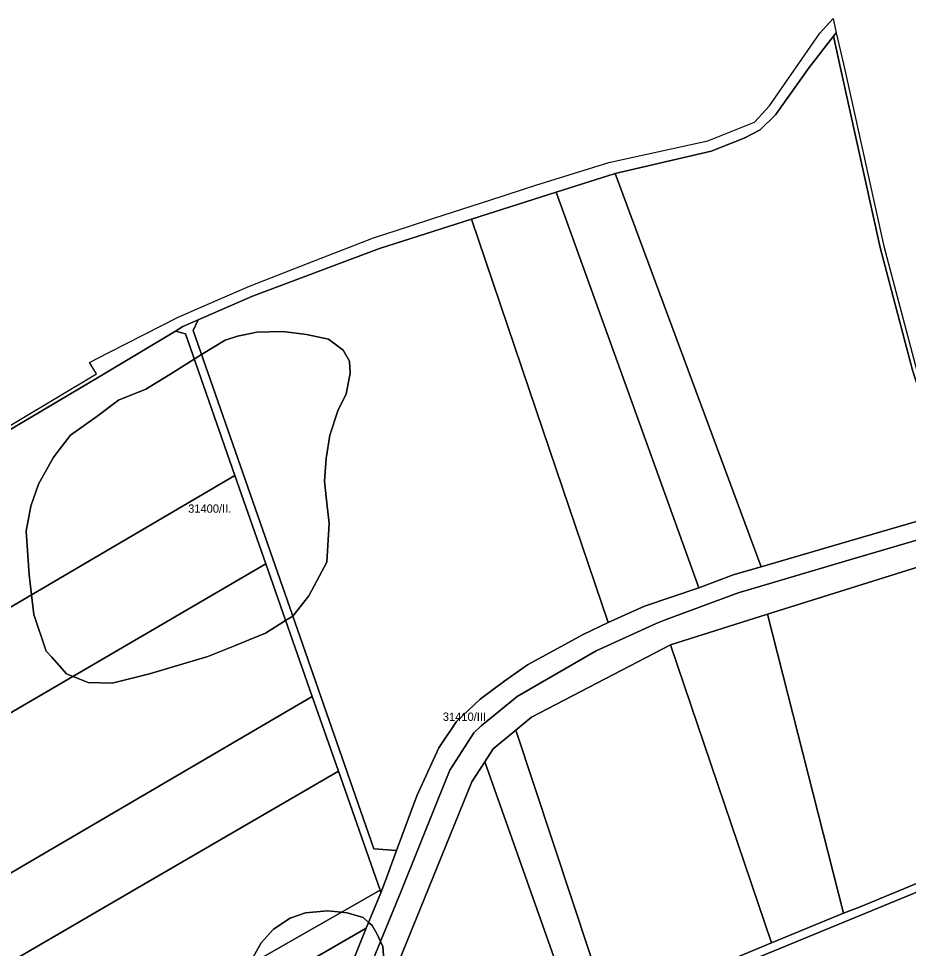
# Model space of a CAD drawing. Extents: x -522079 to -518833, y -1142400 to -1139961.
# Drawn here: x -520538 to -520002, y -1140521 to -1139961 of the extents above; entities that cross this region are included whole.
import ezdxf

# ---------------------------------------------------------------- set-up
doc = ezdxf.new("R2010")
doc.units = 0
for name, color, linetype in [('95560013', 7, 'Continuous'), ('95610013', 7, 'Continuous'), ('95640013', 7, 'Continuous'), ('95660013', 7, 'Continuous')]:
    doc.layers.add(name, color=color, linetype=linetype)

msp = doc.modelspace()

# ---------------------------------------------------------------- linework, layer by layer
at = {"layer": '95560013'}
for points in [[(-520178.95, -1140054.65), (-520121.19, -1140041.17), (-520101.17, -1140033.45), (-520091.68, -1140028.41), (-520082.48, -1140019.36), (-520062.19, -1139990.92), (-520047.4, -1139971.94), (-520042.94, -1139993.02), (-520019.48, -1140099.15), (-519999.86, -1140173.01), (-519972.75, -1140256.9), (-520039.59, -1140276.29), (-520091.03, -1140291.29)], [(-520091.03, -1140291.29), (-520107.24, -1140295.95), (-520128.63, -1140303.97), (-520170.5, -1140187.64), (-520214.32, -1140065.91), (-520178.95, -1140054.65)], [(-520265.37, -1140082.17), (-520214.32, -1140065.91), (-520170.5, -1140187.64), (-520128.63, -1140303.97), (-520161.16, -1140315.09), (-520183.06, -1140324.86), (-520226.42, -1140197.01)], [(-520320.72, -1140099.79), (-520265.37, -1140082.17), (-520226.42, -1140197.01), (-520183.06, -1140324.86), (-520198.24, -1140332), (-520231.71, -1140350.36), (-520245.33, -1140359.99), (-520260.24, -1140370.94), (-520274.33, -1140384.38), (-520285.01, -1140400.23), (-520298.27, -1140429.16), (-520310.52, -1140461.93), (-520324.15, -1140461.03), (-520370.19, -1140328.97), (-520432.89, -1140149.1), (-520429.91, -1140142.73), (-520397.23, -1140128.42)], [(-520432.89, -1140149.1), (-520370.19, -1140328.97), (-520324.15, -1140461.03), (-520310.52, -1140461.93), (-520317.29, -1140480.75), (-520319.85, -1140487.51), (-520320.44, -1140485.82), (-520345.47, -1140414.38), (-520361.23, -1140369.4), (-520389.24, -1140289.48), (-520407.86, -1140236.34), (-520437.53, -1140151.12), (-520443.64, -1140149.48), (-520439.13, -1140146.77), (-520429.91, -1140142.73)], [(-520697.54, -1140405.82), (-520704.93, -1140387.92), (-520719.64, -1140344.89), (-520729.96, -1140323.84), (-520727.12, -1140316.09), (-520610.57, -1140248.68), (-520489.41, -1140176.97), (-520443.64, -1140149.48), (-520437.53, -1140151.12), (-520407.86, -1140236.34), (-520563.45, -1140327.62)], [(-520407.86, -1140236.34), (-520389.24, -1140289.48), (-520535.21, -1140374.77), (-520673.87, -1140455.8), (-520683.48, -1140439.85), (-520697.54, -1140405.82), (-520563.45, -1140327.62)], [(-520087.13, -1140319.85), (-519973.33, -1140284.13), (-519917.2, -1140450.72), (-519949.02, -1140461.79), (-520031.39, -1140495.83), (-520041.44, -1140499.76)], [(-520592.52, -1140504.62), (-520608.7, -1140486.32), (-520623.97, -1140478.75), (-520659.41, -1140472.47), (-520666.98, -1140467.24), (-520673.87, -1140455.8), (-520535.21, -1140374.77), (-520389.24, -1140289.48), (-520361.23, -1140369.4)], [(-520041.44, -1140499.76), (-520084.71, -1140517.54), (-520145.65, -1140338.22), (-520087.13, -1140319.85)], [(-520238.71, -1140389.58), (-520229.31, -1140381.82), (-520145.65, -1140338.22), (-520084.71, -1140517.54), (-520106.55, -1140526.52), (-520182.86, -1140557.87)], [(-520361.23, -1140369.4), (-520345.47, -1140414.38), (-520469.06, -1140486.19), (-520562.49, -1140540.48), (-520587.65, -1140510.13), (-520592.52, -1140504.62)], [(-520182.86, -1140557.87), (-520201.76, -1140565.63), (-520257.35, -1140408.66), (-520252.32, -1140400.85), (-520238.71, -1140389.58)], [(-520201.76, -1140565.63), (-520263.96, -1140591.19), (-520277.29, -1140595.78), (-520289.45, -1140599.87), (-520311.64, -1140535.23), (-520265.09, -1140420.72), (-520257.35, -1140408.66)], [(-520345.47, -1140414.38), (-520320.44, -1140485.82), (-520431.13, -1140549.18), (-520503.8, -1140590.78), (-520557.7, -1140546.26), (-520562.49, -1140540.48), (-520469.06, -1140486.19)], [(-519886.24, -1140527.38), (-520082.56, -1140649.64), (-520126.03, -1140587.59), (-520155.91, -1140552.2), (-520104.66, -1140531.14), (-519947.24, -1140466.47), (-519916.36, -1140457.2), (-519904.17, -1140458.14), (-519893.54, -1140491.71)], [(-520490.09, -1140602.11), (-520503.8, -1140590.78), (-520431.13, -1140549.18), (-520320.44, -1140485.82), (-520319.85, -1140487.51), (-520328.73, -1140508.82)], [(-520459.31, -1140627.54), (-520490.09, -1140602.11), (-520328.73, -1140508.82), (-520342.62, -1140543.01), (-520348.21, -1140563.43)]]:
    msp.add_lwpolyline(points, close=True, dxfattribs=at)
at = {"layer": '95610013'}
for points in [[(-520327.66, -1140534.75), (-520307.77, -1140486.46), (-520286.11, -1140432.61), (-520278.46, -1140413.78), (-520263.92, -1140391.15), (-520259.52, -1140387.05), (-520251.21, -1140380.2), (-520246.72, -1140376.59), (-520237.84, -1140369.42), (-520222.7, -1140360.61), (-520190.37, -1140341.83), (-520154.29, -1140325.48), (-520148.17, -1140323.1), (-520104.17, -1140306.68), (-520102.1, -1140306.15), (-520037.05, -1140286.83), (-519993.22, -1140274.03)], [(-519973.33, -1140284.13), (-520087.13, -1140319.85), (-520145.65, -1140338.22), (-520229.31, -1140381.82), (-520238.71, -1140389.58), (-520252.32, -1140400.85), (-520257.35, -1140408.66), (-520265.09, -1140420.72), (-520311.64, -1140535.23)]]:
    msp.add_lwpolyline(points, dxfattribs=at)
at = {"layer": '95640013'}
for points in [[(-520611.62, -1140247.2), (-520491.09, -1140175.17), (-520495.34, -1140168.3), (-520483.64, -1140162.33), (-520442, -1140141.08), (-520418.53, -1140130.92), (-520398.93, -1140122.43), (-520359.48, -1140107), (-520324.32, -1140093.25), (-520303.34, -1140086.47), (-520288.09, -1140081.53), (-520260.01, -1140072.45), (-520246.26, -1140068.01), (-520233.47, -1140063.87), (-520226.58, -1140061.71), (-520194.98, -1140051.81), (-520182.69, -1140047.96), (-520145.26, -1140039.86), (-520123.02, -1140035.05), (-520094.95, -1140023.82), (-520085.97, -1140013.91), (-520055.62, -1139970.09), (-520047.76, -1139961.42), (-520045.81, -1139969.91), (-520047.4, -1139971.94), (-520062.19, -1139990.92), (-520082.48, -1140019.36), (-520091.68, -1140028.41), (-520101.17, -1140033.45), (-520121.19, -1140041.17), (-520178.95, -1140054.65), (-520214.32, -1140065.91), (-520265.37, -1140082.17), (-520320.72, -1140099.79), (-520397.23, -1140128.42), (-520429.91, -1140142.73), (-520439.13, -1140146.77), (-520443.64, -1140149.48), (-520489.41, -1140176.97), (-520610.57, -1140248.68)], [(-520342.62, -1140543.01), (-520328.73, -1140508.82), (-520319.85, -1140487.51), (-520317.29, -1140480.75), (-520310.52, -1140461.93), (-520298.27, -1140429.16), (-520285.01, -1140400.23), (-520274.33, -1140384.38), (-520260.24, -1140370.94), (-520245.33, -1140359.99), (-520231.71, -1140350.36), (-520198.24, -1140332), (-520183.06, -1140324.86), (-520161.16, -1140315.09), (-520128.63, -1140303.97), (-520107.24, -1140295.95), (-520091.03, -1140291.29), (-520039.59, -1140276.29), (-519972.75, -1140256.9)], [(-519993.22, -1140274.03), (-520037.05, -1140286.83), (-520102.1, -1140306.15), (-520104.17, -1140306.68), (-520148.17, -1140323.1), (-520154.29, -1140325.48), (-520190.37, -1140341.83), (-520222.7, -1140360.61), (-520237.84, -1140369.42), (-520246.72, -1140376.59), (-520251.21, -1140380.2), (-520259.52, -1140387.05), (-520263.92, -1140391.15), (-520278.46, -1140413.78), (-520286.11, -1140432.61), (-520307.77, -1140486.46), (-520327.66, -1140534.75)], [(-519947.24, -1140466.47), (-520104.66, -1140531.14), (-520155.91, -1140552.2), (-520167.57, -1140556.99), (-520262.2, -1140595.87), (-520287.56, -1140604.5), (-520318.61, -1140618.22), (-520330.21, -1140624.54), (-520334.77, -1140627.95), (-520334.5, -1140634.63), (-520342.44, -1140624.55), (-520317.54, -1140611.38), (-520303.27, -1140605.8), (-520289.45, -1140599.87), (-520277.29, -1140595.78), (-520263.96, -1140591.19), (-520201.76, -1140565.63), (-520182.86, -1140557.87), (-520106.55, -1140526.52), (-520084.71, -1140517.54), (-520041.44, -1140499.76), (-520031.39, -1140495.83), (-519949.02, -1140461.79)]]:
    msp.add_lwpolyline(points, dxfattribs=at)
msp.add_lwpolyline([(-520044.21, -1139976.9), (-520040.68, -1139992.3), (-520017.23, -1140098.3), (-519997.42, -1140172.65), (-519970.54, -1140256.24), (-519972.75, -1140256.9), (-519999.86, -1140173.01), (-520019.48, -1140099.15), (-520042.94, -1139993.02), (-520047.4, -1139971.94), (-520045.81, -1139969.91)], close=True, dxfattribs=at)
at = {"layer": '95660013'}
for points in [[(-520611.62, -1140247.2), (-520491.09, -1140175.17), (-520495.34, -1140168.3), (-520483.64, -1140162.33), (-520442, -1140141.08), (-520418.53, -1140130.92), (-520398.93, -1140122.43), (-520359.48, -1140107), (-520324.32, -1140093.25), (-520303.34, -1140086.47), (-520288.09, -1140081.53), (-520260.01, -1140072.45), (-520246.26, -1140068.01), (-520233.47, -1140063.87), (-520226.58, -1140061.71), (-520194.98, -1140051.81), (-520182.69, -1140047.96), (-520145.26, -1140039.86), (-520123.02, -1140035.05), (-520094.95, -1140023.82), (-520085.97, -1140013.91), (-520055.62, -1139970.09), (-520047.76, -1139961.42), (-520045.81, -1139969.91), (-520044.21, -1139976.9), (-520040.68, -1139992.3), (-520017.23, -1140098.3), (-519997.42, -1140172.65)], [(-520398.63, -1140529.45), (-520391.98, -1140517.59), (-520384.59, -1140509.44), (-520374.62, -1140502.77), (-520365.38, -1140499.44), (-520352.08, -1140498.33), (-520343.67, -1140499.11), (-520340.26, -1140499.44), (-520330.66, -1140502.4), (-520327.28, -1140505.34), (-520325.12, -1140507.22), (-520322.16, -1140512.41), (-520320.23, -1140516.71), (-520318.84, -1140519.82), (-520318.1, -1140527.97)], [(-520318.1, -1140527.97), (-520318.84, -1140519.82), (-520320.23, -1140516.71), (-520322.16, -1140512.41), (-520325.12, -1140507.22), (-520327.28, -1140505.34), (-520330.66, -1140502.4), (-520340.26, -1140499.44), (-520343.67, -1140499.11), (-520352.08, -1140498.33), (-520365.38, -1140499.44), (-520374.62, -1140502.77), (-520384.59, -1140509.44), (-520391.98, -1140517.59), (-520398.63, -1140529.45)]]:
    msp.add_lwpolyline(points, dxfattribs=at)
for points in [[(-520459.11, -1140355.71), (-520481.57, -1140361.34), (-520496.07, -1140360.87), (-520505.24, -1140357.26), (-520509.17, -1140355.71), (-520518.05, -1140345.78), (-520521.34, -1140342.1), (-520528.82, -1140320.04), (-520530.22, -1140308.12), (-520531.63, -1140296.1), (-520533.5, -1140269.82), (-520530.69, -1140254.8), (-520526.02, -1140241.66), (-520517.13, -1140225.7), (-520513.57, -1140221), (-520506.83, -1140212.09), (-520490.93, -1140200.83), (-520477.83, -1140190.98), (-520461.45, -1140184.41), (-520446.95, -1140175.49), (-520432.23, -1140166.34), (-520427.83, -1140163.6), (-520413.73, -1140154.84), (-520406.24, -1140152.49), (-520402.25, -1140151.69), (-520394.55, -1140150.14), (-520379.11, -1140149.67), (-520370.99, -1140150.73), (-520367.65, -1140151.16), (-520364.6, -1140151.55), (-520351.5, -1140154.36), (-520342.61, -1140160.94), (-520338.87, -1140167.51), (-520338.4, -1140175.02), (-520340.74, -1140187.22), (-520345.89, -1140197.54), (-520350.57, -1140212.09), (-520352.91, -1140226.17), (-520353.27, -1140231.49), (-520353.84, -1140239.78), (-520352.18, -1140254.84), (-520351.04, -1140265.13), (-520352.44, -1140288.6), (-520363.2, -1140308.77), (-520372.99, -1140320.94), (-520377.26, -1140323.65), (-520389.4, -1140331.31), (-520408.03, -1140338.88), (-520424.02, -1140345.38)], [(-520533.5, -1140269.82), (-520531.63, -1140296.1), (-520530.22, -1140308.12), (-520528.82, -1140320.04), (-520521.34, -1140342.1), (-520518.05, -1140345.78), (-520509.17, -1140355.71), (-520505.24, -1140357.26), (-520496.07, -1140360.87), (-520481.57, -1140361.34), (-520459.11, -1140355.71), (-520424.02, -1140345.38), (-520408.03, -1140338.88), (-520389.4, -1140331.31), (-520377.26, -1140323.65), (-520372.99, -1140320.94), (-520363.2, -1140308.77), (-520352.44, -1140288.6), (-520351.04, -1140265.13), (-520352.18, -1140254.84), (-520353.84, -1140239.78), (-520353.27, -1140231.49), (-520352.91, -1140226.17), (-520350.57, -1140212.09), (-520345.89, -1140197.54), (-520340.74, -1140187.22), (-520338.4, -1140175.02), (-520338.87, -1140167.51), (-520342.61, -1140160.94), (-520351.5, -1140154.36), (-520364.6, -1140151.55), (-520367.65, -1140151.16), (-520370.99, -1140150.73), (-520379.11, -1140149.67), (-520394.55, -1140150.14), (-520402.25, -1140151.69), (-520406.24, -1140152.49), (-520413.73, -1140154.84), (-520427.83, -1140163.6), (-520432.23, -1140166.34), (-520446.95, -1140175.49), (-520461.45, -1140184.41), (-520477.83, -1140190.98), (-520490.93, -1140200.83), (-520506.83, -1140212.09), (-520513.57, -1140221), (-520517.13, -1140225.7), (-520526.02, -1140241.66), (-520530.69, -1140254.8)]]:
    msp.add_lwpolyline(points, close=True, dxfattribs=at)

# ---------------------------------------------------------------- texts
for s, p in [('31400/II.', (-520435.95, -1140258.77)), ('31410/III.', (-520282.64, -1140384.02))]:
    msp.add_text(s, height=5, rotation=0, dxfattribs=at).set_placement(p)

doc.saveas('drawing.dxf')
